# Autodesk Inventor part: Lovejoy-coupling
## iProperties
Author: Ole Germer
Shininess: 25.0
PropertySet Name: _Private Model Information
Created: 2001-03
Part Number: Lovejoy-coupling
Document SubType Name: Modeling
Designer: Ole Germer
Material: Steel, Mild
Control State: 0
Master: False
Checked Out: False
PropertySet Name: Design Tracking Control
Density: 7.86
Volumn: 32.06660363322067
Area: 83.40977722701146
PropertySet Name: Model Information
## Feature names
1. Extrusion1
2. Extrusion2
3. Extrusion3
4. Extrusion7
5. Extrusion5
6. Hole1
